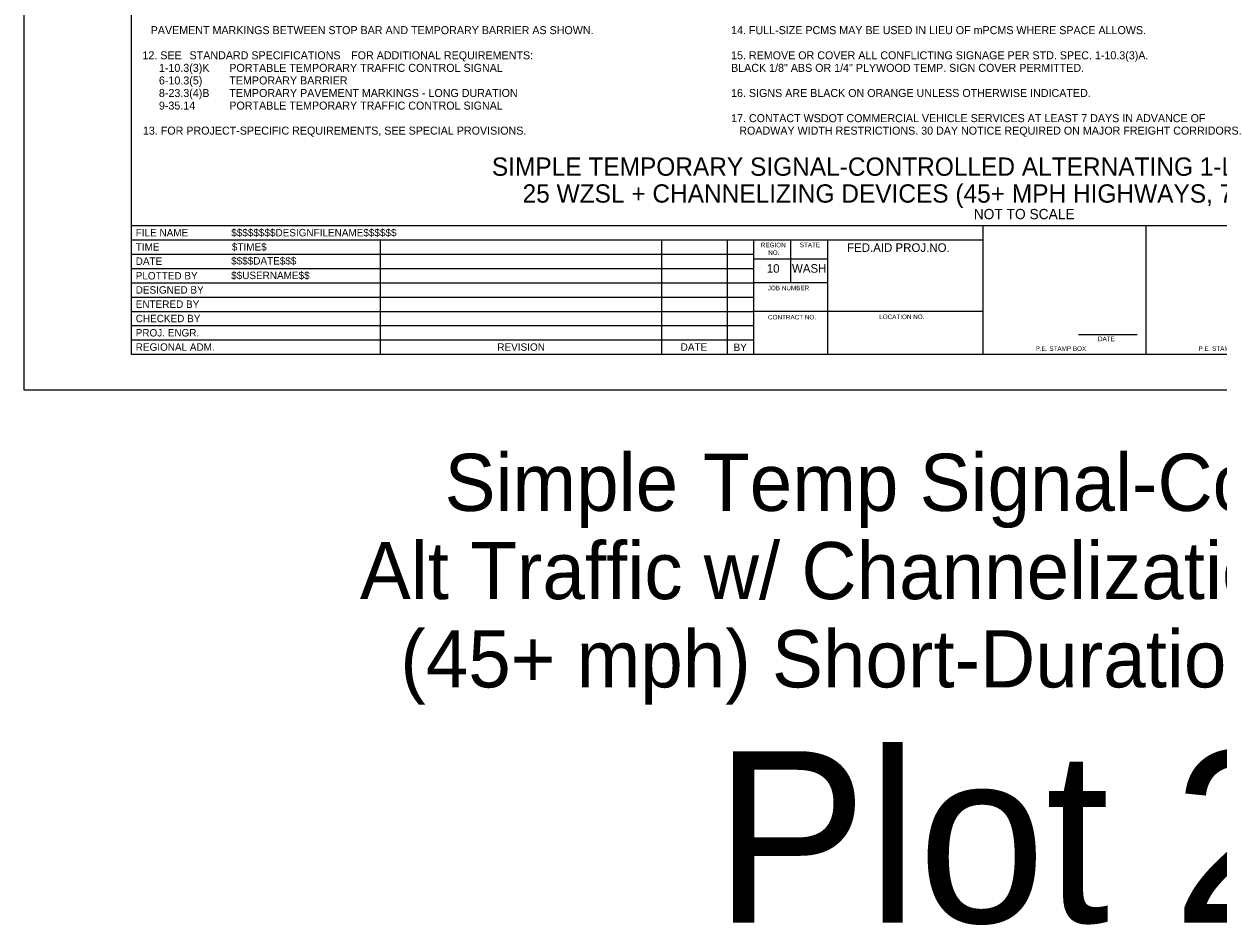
# Model space of a CAD drawing. Extents: x 99979.8 to 100075.7, y 99995 to 100010.7.
# Drawn here: x 100019.06 to 100029.51, y 99995.01 to 100002.89 of the extents above; entities that cross this region are included whole.
import ezdxf

# ---------------------------------------------------------------- set-up
doc = ezdxf.new("R2010")
doc.units = 0
for name, color, linetype in [('SH_DE_DetailHeading1Text', 7, 'Continuous'), ('SH_GI_GeneralNotesBodyText', 7, 'Continuous'), ('SH_GI_PlotLimits', 7, 'Continuous'), ('SH_GI_SheetBorder', 7, 'Continuous'), ('SH_GI_SheetLocationText', 7, 'Continuous'), ('SH_GI_SheetTextInCells', 7, 'Continuous'), ('SH_GI_TitleBlockText', 7, 'Continuous')]:
    doc.layers.add(name, color=color, linetype=linetype)

msp = doc.modelspace()

# ---------------------------------------------------------------- linework, layer by layer
at = {"layer": 'SH_GI_PlotLimits'}
msp.add_lwpolyline([(100019.062, 99999.687), (100036.062, 99999.687), (100036.062, 100010.687), (100019.062, 100010.687)], close=True, dxfattribs=at)
at = {"layer": 'SH_GI_SheetBorder'}
for p, q in [((100020, 100010.375), (100020, 100000)), ((100020, 100001.126), (100035.75, 100001.126)), ((100027.457, 100000), (100027.457, 100001.126)), ((100028.883, 100000), (100028.883, 100001.126)), ((100020, 100001.001), (100027.457, 100001.001)), ((100022.179, 100001.001), (100022.179, 100000)), ((100024.641, 100001.001), (100024.641, 100000)), ((100025.216, 100001.001), (100025.216, 100000)), ((100025.445, 100001.001), (100025.445, 100000)), ((100025.772, 100000.625), (100025.772, 100001.001)), ((100026.096, 100000), (100026.096, 100001.001)), ((100020, 100000.876), (100022.182, 100000.876)), ((100022.182, 100000.876), (100025.447, 100000.876)), ((100026.096, 100000.831), (100025.447, 100000.831)), ((100020, 100000.751), (100022.182, 100000.751)), ((100022.182, 100000.751), (100025.447, 100000.751)), ((100020, 100000.625), (100025.447, 100000.625)), ((100026.096, 100000.625), (100025.447, 100000.625)), ((100020, 100000.5), (100025.447, 100000.5)), ((100020, 100000.375), (100025.447, 100000.375)), ((100027.457, 100000.375), (100025.447, 100000.375)), ((100020, 100000.25), (100025.447, 100000.25)), ((100020, 100000.125), (100025.447, 100000.125)), ((100028.29, 100000.173), (100028.802, 100000.173)), ((100020, 100000), (100035.75, 100000))]:
    msp.add_line(p, q, dxfattribs=at)

# ---------------------------------------------------------------- texts
at = {"layer": 'SH_DE_DetailHeading1Text'}
for s, height, p in [('SIMPLE TEMPORARY SIGNAL-CONTROLLED ALTERNATING 1-LANE, 2-WAY TRAFFIC', 0.16, (100023.157, 100001.561)), ('25 WZSL + CHANNELIZING DEVICES (45+ MPH HIGHWAYS, 7 DAYS OR LESS)', 0.16, (100023.426, 100001.326)), ('NOT TO SCALE', 0.09, (100027.373, 100001.181))]:
    msp.add_text(s, height=height, rotation=360, dxfattribs=at).set_placement(p)
at = {"layer": 'SH_GI_GeneralNotesBodyText'}
for s, p in [('PAVEMENT MARKINGS BETWEEN STOP BAR AND TEMPORARY BARRIER AS SHOWN.', (100020.172, 100002.8)), ('14. FULL-SIZE PCMS MAY BE USED IN LIEU OF mPCMS WHERE SPACE ALLOWS.', (100025.25, 100002.8)), ('12. SEE ', (100020.1, 100002.58)), ('STANDARD SPECIFICATIONS', (100020.512, 100002.58)), (' FOR ADDITIONAL REQUIREMENTS:', (100021.9, 100002.58)), ('15. REMOVE OR COVER ALL CONFLICTING SIGNAGE PER STD. SPEC. 1-10.3(3)A. ', (100025.25, 100002.58)), ('1-10.3(3)K', (100020.244, 100002.47)), ('PORTABLE TEMPORARY TRAFFIC CONTROL SIGNAL', (100020.86, 100002.47)), ('BLACK 1/8" ABS OR 1/4" PLYWOOD TEMP. SIGN COVER PERMITTED.', (100025.25, 100002.47)), ('6-10.3(5)', (100020.244, 100002.36)), ('TEMPORARY BARRIER', (100020.86, 100002.36)), ('8-23.3(4)B', (100020.244, 100002.25)), ('TEMPORARY PAVEMENT MARKINGS - LONG DURATION', (100020.86, 100002.25)), ('16. SIGNS ARE BLACK ON ORANGE UNLESS OTHERWISE INDICATED.', (100025.25, 100002.25)), ('9-35.14', (100020.244, 100002.14)), ('PORTABLE TEMPORARY TRAFFIC CONTROL SIGNAL', (100020.86, 100002.14)), ('17. CONTACT WSDOT COMMERCIAL VEHICLE SERVICES AT LEAST 7 DAYS IN ADVANCE OF ', (100025.25, 100002.03)), ('13. FOR PROJECT-SPECIFIC REQUIREMENTS, SEE SPECIAL PROVISIONS.', (100020.104, 100001.921)), ('ROADWAY WIDTH RESTRICTIONS. 30 DAY NOTICE REQUIRED ON MAJOR FREIGHT CORRIDORS.', (100025.322, 100001.921))]:
    msp.add_text(s, height=0.07, rotation=360, dxfattribs=at).set_placement(p)
at = {"layer": 'SH_GI_SheetLocationText'}
for s, height, p in [('Simple', 0.5, (100022.743, 99998.629)), (' Temp Signal-Controlled', 0.5, (100024.819, 99998.629)), ('Alt Traffic w/ Channelization Devices', 0.5, (100022.002, 99997.857)), ('(45+ mph) Short-Duration Version', 0.5, (100022.356, 99997.085)), ('Plot 2', 1.5, (100025.102, 99995.027))]:
    msp.add_text(s, height=height, dxfattribs=at).set_placement(p)
at = {"layer": 'SH_GI_SheetTextInCells'}
for s, height, p in [('FILE NAME', 0.0651, (100020.041, 100001.031)), ('TIME', 0.0651, (100020.041, 100000.906)), ('REGION', 0.04, (100025.51, 100000.935)), ('STATE', 0.04, (100025.851, 100000.936)), ('FED.AID PROJ.NO.', 0.07506, (100026.265, 100000.895)), ('DATE', 0.0651, (100020.041, 100000.781)), ('NO.', 0.04, (100025.575, 100000.869)), ('PLOTTED BY', 0.0651, (100020.041, 100000.654)), ('10', 0.0751, (100025.562, 100000.713)), ('WASH', 0.0751, (100025.783, 100000.713)), ('DESIGNED BY', 0.06505, (100020.041, 100000.53)), ('JOB NUMBER', 0.04, (100025.571, 100000.559)), ('ENTERED BY', 0.0651, (100020.041, 100000.405)), ('CHECKED BY', 0.0651, (100020.041, 100000.28)), ('CONTRACT NO.', 0.04003, (100025.573, 100000.304)), ('LOCATION NO.', 0.04003, (100026.546, 100000.307)), ('PROJ. ENGR.', 0.06505, (100020.041, 100000.155)), ('REGIONAL ADM.', 0.06505, (100020.041, 100000.03)), ('REVISION', 0.0651, (100023.205, 100000.03)), ('DATE', 0.0651, (100024.809, 100000.03)), ('BY', 0.0651, (100025.272, 100000.028)), ('DATE', 0.04, (100028.46, 100000.114)), ('P.E. STAMP BOX', 0.04003, (100027.915, 100000.029)), ('P.E. STAMP BOX', 0.04003, (100029.339, 100000.029))]:
    msp.add_text(s, height=height, dxfattribs=at).set_placement(p)
at = {"layer": 'SH_GI_TitleBlockText'}
for s, height, p in [('$$$$$$$$DESIGNFILENAME$$$$$$', 0.06505, (100020.877, 100001.031)), ('$TIME$', 0.0651, (100020.882, 100000.906)), ('$$$$DATE$$$', 0.06505, (100020.876, 100000.784)), ('$$USERNAME$$', 0.06505, (100020.876, 100000.657))]:
    msp.add_text(s, height=height, dxfattribs=at).set_placement(p)

doc.saveas('drawing.dxf')
